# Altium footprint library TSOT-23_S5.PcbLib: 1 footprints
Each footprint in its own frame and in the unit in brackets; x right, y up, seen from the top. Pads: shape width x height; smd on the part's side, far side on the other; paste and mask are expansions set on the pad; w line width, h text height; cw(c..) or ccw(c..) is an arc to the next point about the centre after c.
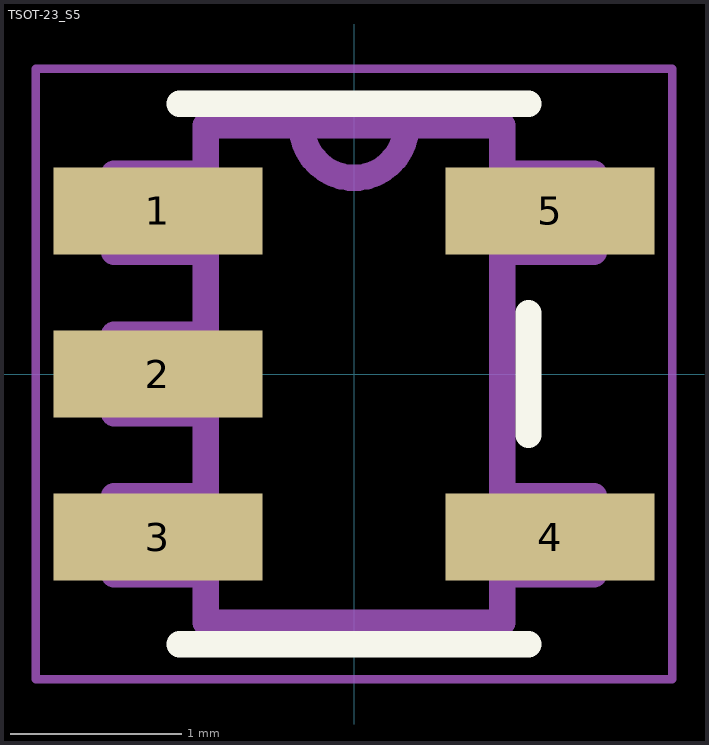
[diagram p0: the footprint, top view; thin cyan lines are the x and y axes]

## TSOT-23_S5 [mil]
pads (5):
  rect 48x20 smd: 1(-45,37.4) 2(-45,0) 3(-45,-37.4) 4(45,-37.4) 5(45,37.4)
Top Overlay:
  lines w6: -40,-62 40,-62 ; -40,62 40,62 ; 40,-14 40,14
Assembly Top:
  lines w6: -12,57 ccw(c0,57) 12,57 ; -12,57 12,57 ; -12,57 -34,57 -34,-57 34,-57 34,57 12,57 ; -55,-46 -55,-28 -34,-28 -34,-46 -55,-46 ; -55,-9 -55,9 -34,9 -34,-9 -55,-9 ; -55,28 -55,46 -34,46 -34,28 -55,28 ; 34,-46 34,-28 55,-28 55,-46 34,-46 ; 34,28 34,46 55,46 55,28 34,28
Courtyard Top:
  lines w1.97: -73,-70 -73,70 73,70 73,-70 -73,-70
3D body "step_temp.STEP": height 39.37, standoff 0, extent -55.12,-57.09 55.12,57.09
